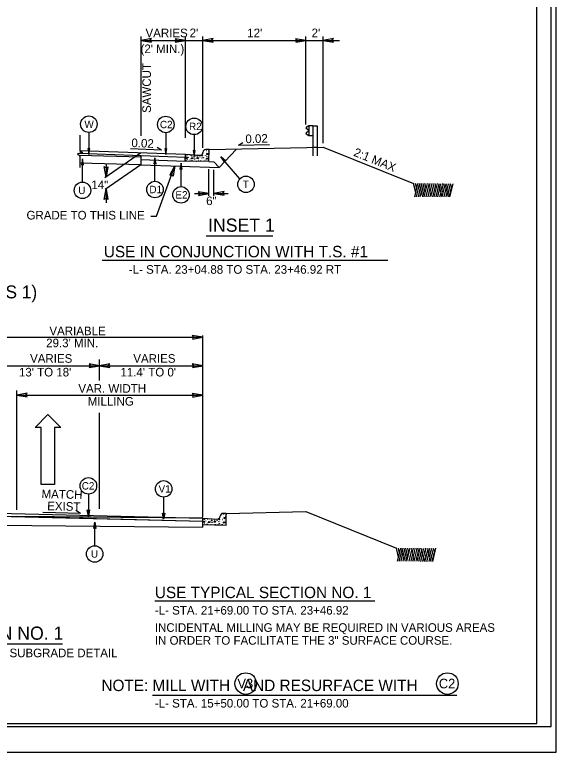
# Model space of a CAD drawing. Extents: x 573748 to 574632, y -54663 to -53209.
# Drawn here: x 574186.6 to 574281, y -53428.7 to -53300 of the extents above; entities that cross this region are included whole.
import ezdxf

# ---------------------------------------------------------------- set-up
doc = ezdxf.new("R2010")
doc.units = 0
for name, color, linetype in [('Prop Dimension', 7, 'Continuous'), ('Prop Dimension Text', 7, 'Continuous'), ('Prop Lane Arrow CELL', 7, 'Continuous'), ('Prop Terminator CELL', 7, 'Continuous'), ('Sheet Cutting Line CELL', 7, 'Continuous'), ('Sheet Plot Border Inside CELL', 7, 'Continuous'), ('Sheet Plot Border Outside CELL', 7, 'Continuous'), ('Sheet Typical CELL', 7, 'Continuous'), ('Typical Arrow Superelevation CELL', 7, 'Continuous'), ('Typical Curb CELL', 7, 'Continuous'), ('Typical Guardrail CELL', 7, 'Continuous'), ('Typical Hinge Slope Arterial CELL', 7, 'Continuous'), ('Typical ID Circle CELL', 7, 'Continuous'), ('Typical Pavement Slope CELL', 7, 'Continuous'), ('Typical Slope Point Local CELL', 7, 'Continuous'), ('Typical Terminator CELL', 7, 'Continuous'), ('Typical Text General CELL', 7, 'Continuous'), ('Typical Text ID Circle CELL', 7, 'Continuous'), ('Typical Text Label CELL', 7, 'Continuous')]:
    doc.layers.add(name, color=color, linetype=linetype)

msp = doc.modelspace()

# ---------------------------------------------------------------- linework, layer by layer
at = {"layer": 'Prop Dimension'}
for p, q in [((574208.6, -53321.18), (574208.6, -53303.84)), ((574216.33, -53321.5), (574216.33, -53303.84)), ((574219.33, -53323.24), (574219.33, -53303.84)), ((574237.33, -53319.18), (574237.33, -53303.84)), ((574240.33, -53322.43), (574240.33, -53303.84)), ((574208.6, -53304.5), (574216.33, -53304.5)), ((574216.33, -53304.5), (574219.33, -53304.5)), ((574219.33, -53304.5), (574237.33, -53304.5)), ((574237.33, -53304.5), (574243.16, -53304.5)), ((574197.88, -53321.01), (574197.88, -53323.78)), ((574198.38, -53324.08), (574197.52, -53324.27)), ((574197.52, -53324.27), (574197.88, -53324.62)), ((574197.77, -53324.52), (574208.6, -53324.8)), ((574197.88, -53323.78), (574198.38, -53324.08)), ((574197.88, -53324.62), (574197.88, -53326.68)), ((574208.48, -53324.17), (574202.29, -53328.47)), ((574197.88, -53325.87), (574208.6, -53326.14)), ((574208.56, -53326.22), (574202.35, -53330.54)), ((574202.48, -53325.99), (574202.48, -53328.34)), ((574208.6, -53326.14), (574208.6, -53325.92)), ((574220.38, -53331.64), (574220.38, -53326.95)), ((574221.27, -53331.64), (574221.27, -53327.1)), ((574202.48, -53330.45), (574202.48, -53332.85)), ((574217.87, -53331.21), (574220.38, -53331.21)), ((574221.27, -53331.21), (574223.77, -53331.21)), ((574174.33, -53356.27), (574219.33, -53356.27)), ((574219.33, -53387.71), (574219.33, -53356.01)), ((574201.33, -53363.84), (574201.33, -53360.17)), ((574183.33, -53361.26), (574201.33, -53361.26)), ((574201.33, -53361.26), (574219.33, -53361.26)), ((574186.93, -53386.44), (574186.93, -53365.58)), ((574186.93, -53366.41), (574219.33, -53366.41)), ((574201.33, -53386.26), (574201.33, -53369.46)), ((574219.33, -53387.86), (574174.33, -53387.48)), ((574219.33, -53389.03), (574219.33, -53387.86)), ((574219.33, -53387.86), (574221.84, -53388.02)), ((574219.33, -53388.11), (574219.33, -53387.86)), ((574219.33, -53387.86), (574219.33, -53387.86)), ((574222.37, -53387.54), (574222.37, -53387.51)), ((574223.43, -53387.04), (574222.89, -53387.03)), ((574223.02, -53387.73), (574223.05, -53387.92)), ((574223.34, -53387.83), (574223.02, -53387.73)), ((574223.05, -53387.92), (574223.34, -53387.83)), ((574223.43, -53387.04), (574237.33, -53386.73)), ((574223.43, -53389.14), (574223.43, -53387.04)), ((574237.33, -53386.73), (574253.1, -53393.1)), ((574174.33, -53389), (574219.33, -53389.45)), ((574219.33, -53389.45), (574219.33, -53389.03)), ((574223.43, -53389.14), (574219.33, -53389.03)), ((574219.37, -53388.56), (574219.55, -53388.32)), ((574219.62, -53388.56), (574219.37, -53388.56)), ((574219.55, -53388.32), (574219.62, -53388.56)), ((574220.3, -53388.66), (574220.44, -53388.42)), ((574220.65, -53388.59), (574220.3, -53388.66)), ((574220.44, -53388.42), (574220.65, -53388.59)), ((574221.32, -53388.58), (574221.5, -53388.33)), ((574221.57, -53388.57), (574221.32, -53388.58)), ((574221.5, -53388.33), (574221.57, -53388.57)), ((574222.92, -53388.73), (574223.05, -53388.49)), ((574223.27, -53388.65), (574222.92, -53388.73)), ((574223.05, -53388.49), (574223.27, -53388.65)), ((574253.48, -53394.65), (574253.1, -53393.1)), ((574253.3, -53395.38), (574253.86, -53393.09)), ((574253.65, -53393.96), (574253.44, -53393.1)), ((574254.7, -53395.38), (574254.13, -53393.1)), ((574254.7, -53394.16), (574254.44, -53393.1)), ((574255.12, -53394.63), (574254.74, -53393.1)), ((574254.93, -53395.38), (574255.5, -53393.1)), ((574255.28, -53393.97), (574255.07, -53393.1)), ((574256.38, -53395.38), (574255.81, -53393.1)), ((574256.71, -53395.32), (574256.17, -53393.1)), ((574256.89, -53394.61), (574256.52, -53393.1)), ((574256.7, -53395.38), (574257.26, -53393.1)), ((574257.05, -53393.94), (574256.84, -53393.1)), ((574258.07, -53395.42), (574257.5, -53393.13)), ((574258.16, -53394.56), (574257.8, -53393.13)), ((574258.07, -53394.1), (574258.31, -53393.13)), ((574258.16, -53393.24), (574258.13, -53393.13)), ((574258.2, -53393.2), (574258.17, -53393.1)), ((574259.17, -53395.42), (574258.59, -53393.13)), ((574259.44, -53395.35), (574258.89, -53393.13)), ((574259.61, -53394.69), (574259.22, -53393.13)), ((574259.43, -53395.42), (574259.99, -53393.12)), ((574259.78, -53394), (574259.56, -53393.13)), ((574253.6, -53395.38), (574254.15, -53393.17)), ((574253.94, -53395.38), (574254.31, -53393.82)), ((574254.97, -53395.24), (574254.7, -53394.16)), ((574255.3, -53395.38), (574255.84, -53393.2)), ((574255.65, -53395.38), (574256.01, -53393.9)), ((574257.04, -53395.38), (574257.57, -53393.21)), ((574257.34, -53395.42), (574257.7, -53393.94)), ((574258.09, -53393.97), (574258.07, -53393.88)), ((574258.08, -53395.42), (574258.62, -53393.25)), ((574258.43, -53395.42), (574258.8, -53393.94)), ((574254.26, -53395.38), (574254.48, -53394.48)), ((574255.99, -53395.38), (574256.18, -53394.59)), ((574257.7, -53395.42), (574257.88, -53394.65)), ((574258.79, -53395.42), (574258.97, -53394.65))]:
    msp.add_line(p, q, dxfattribs=at)
for points in [[(574210.26, -53335.17), (574211.28, -53335.17), (574214.48, -53326.41)], [(574219.33, -53387.86), (574186.93, -53387.58), (574219.33, -53388.37), (574219.33, -53388.11)]]:
    msp.add_lwpolyline(points, dxfattribs=at)
for centre in [(574219.66, -53387.96), (574222.95, -53387.19), (574223.28, -53387.65), (574223.4, -53387.27), (574219.37, -53388.92), (574219.38, -53388.1), (574219.62, -53388.75), (574219.62, -53388.07), (574219.73, -53388.99), (574219.82, -53388.37), (574220.1, -53388.87), (574220.2, -53388.04), (574220.45, -53388.15), (574220.46, -53388.96), (574220.78, -53389.01), (574220.81, -53388.36), (574220.85, -53388.16), (574220.92, -53388.66), (574220.97, -53388.23), (574221.13, -53388.57), (574221.2, -53388.04), (574221.22, -53389.07), (574221.4, -53388.16), (574221.56, -53388.93), (574221.81, -53388.09), (574221.86, -53388.3), (574221.99, -53388.99), (574222.17, -53388.49), (574222.24, -53388.13), (574222.23, -53388.82), (574222.28, -53388.03), (574222.35, -53389.06), (574222.43, -53388.44), (574222.72, -53388.94), (574222.81, -53388.1), (574223.06, -53388.22), (574223.08, -53389.03)]:
    msp.add_circle(centre, 0.0168, dxfattribs=at)
for centre, start, end in [((574221.87, -53387.52), 266.1351, 358.5196), ((574222.87, -53387.53), 88.5196, 178.5196)]:
    msp.add_arc(centre, 0.502, start, end, dxfattribs=at)
at = {"layer": 'Prop Lane Arrow CELL'}
for p, q in [((574190.09, -53372.02), (574192.3, -53369.78)), ((574192.3, -53369.78), (574194.58, -53372.02)), ((574191.16, -53372.02), (574190.09, -53372.02)), ((574191.16, -53382), (574191.16, -53372.02)), ((574194.58, -53372.02), (574193.51, -53372.02)), ((574193.51, -53372.02), (574193.51, -53382)), ((574193.51, -53382), (574191.16, -53382))]:
    msp.add_line(p, q, dxfattribs=at)
at = {"layer": 'Prop Terminator CELL'}
for points in [[(574210.4, -53304.17), (574208.6, -53304.5), (574210.42, -53304.8), (574210.18, -53304.48)], [(574214.54, -53304.83), (574216.33, -53304.5), (574214.52, -53304.2), (574214.75, -53304.52)], [(574221.13, -53304.17), (574219.33, -53304.5), (574221.15, -53304.8), (574220.91, -53304.48)], [(574235.54, -53304.83), (574237.33, -53304.5), (574235.52, -53304.2), (574235.75, -53304.52)], [(574242.13, -53304.17), (574240.33, -53304.5), (574242.15, -53304.8), (574241.91, -53304.48)], [(574202.79, -53326.54), (574202.48, -53328.34), (574202.16, -53326.53), (574202.48, -53326.76)], [(574213.57, -53328), (574214.48, -53326.41), (574214.16, -53328.22), (574213.94, -53327.9)], [(574202.17, -53332.25), (574202.48, -53330.45), (574202.8, -53332.26), (574202.48, -53332.03)], [(574218.58, -53331.54), (574220.38, -53331.21), (574218.56, -53330.91), (574218.8, -53331.23)], [(574223.07, -53330.87), (574221.27, -53331.21), (574223.08, -53331.5), (574222.85, -53331.19)], [(574217.54, -53356.61), (574219.33, -53356.27), (574217.52, -53355.98), (574217.75, -53356.29)], [(574199.54, -53361.59), (574201.33, -53361.26), (574199.52, -53360.96), (574199.75, -53361.28)], [(574203.13, -53360.92), (574201.33, -53361.26), (574203.15, -53361.55), (574202.91, -53361.24)], [(574217.54, -53361.59), (574219.33, -53361.26), (574217.52, -53360.96), (574217.75, -53361.28)], [(574188.72, -53366.07), (574186.93, -53366.41), (574188.74, -53366.7), (574188.51, -53366.39)], [(574217.54, -53366.74), (574219.33, -53366.41), (574217.52, -53366.11), (574217.75, -53366.43)]]:
    msp.add_lwpolyline(points, close=True, dxfattribs=at)
at = {"layer": 'Sheet Cutting Line CELL'}
msp.add_line((573944.17, -53428.71), (574280.97, -53428.71), dxfattribs=at)
at = {"layer": 'Sheet Plot Border Inside CELL'}
msp.add_lwpolyline([(574280.07, -53213.2), (573946.77, -53213.2), (573946.77, -53424.22), (574280.07, -53424.22)], close=True, dxfattribs=at)
at = {"layer": 'Sheet Plot Border Outside CELL'}
msp.add_lwpolyline([(574280.97, -53208.71), (573944.17, -53208.71), (573944.17, -53428.71), (574280.97, -53428.71)], close=True, dxfattribs=at)
at = {"layer": 'Sheet Typical CELL'}
msp.add_lwpolyline([(574277.57, -53213.71), (573977.57, -53213.71), (573977.57, -53423.71), (574277.57, -53423.71)], close=True, dxfattribs=at)
at = {"layer": 'Typical Arrow Superelevation CELL'}
for p, q in [((574225.57, -53322.81), (574226.35, -53322.33)), ((574212.15, -53323.67), (574206.76, -53323.44)), ((574212.15, -53323.67), (574211.38, -53323.18)), ((574225.57, -53322.81), (574230.97, -53322.67)), ((574198, -53387.03), (574197.22, -53386.55)), ((574198, -53387.03), (574191.48, -53386.87))]:
    msp.add_line(p, q, dxfattribs=at)
at = {"layer": 'Typical Curb CELL'}
for p, q in [((574220.43, -53323.56), (574219.89, -53323.55)), ((574220.38, -53325.66), (574220.43, -53323.56)), ((574216.3, -53325.55), (574216.33, -53324.38)), ((574216.33, -53324.38), (574218.84, -53324.55)), ((574216.37, -53325.09), (574216.55, -53324.84)), ((574216.55, -53324.84), (574216.62, -53325.08)), ((574218.32, -53325.1), (574218.5, -53324.85)), ((574218.5, -53324.85), (574218.57, -53325.09)), ((574219.37, -53324.06), (574219.37, -53324.04)), ((574220.02, -53324.25), (574220.05, -53324.44)), ((574220.34, -53324.35), (574220.02, -53324.25)), ((574220.05, -53324.44), (574220.34, -53324.35)), ((574220.38, -53325.66), (574216.3, -53325.55)), ((574216.62, -53325.08), (574216.37, -53325.09)), ((574217.3, -53325.18), (574217.44, -53324.95)), ((574217.65, -53325.11), (574217.3, -53325.18)), ((574217.44, -53324.95), (574217.65, -53325.11)), ((574218.57, -53325.09), (574218.32, -53325.1)), ((574219.92, -53325.25), (574220.05, -53325.01)), ((574220.27, -53325.18), (574219.92, -53325.25)), ((574220.05, -53325.01), (574220.27, -53325.18))]:
    msp.add_line(p, q, dxfattribs=at)
for centre in [(574216.38, -53324.62), (574216.62, -53324.59), (574216.66, -53324.48), (574216.82, -53324.89), (574217.2, -53324.56), (574217.45, -53324.67), (574217.81, -53324.88), (574217.85, -53324.68), (574217.97, -53324.76), (574218.2, -53324.57), (574218.4, -53324.68), (574218.81, -53324.61), (574218.86, -53324.83), (574219.24, -53324.66), (574219.28, -53324.55), (574219.81, -53324.63), (574219.95, -53323.71), (574220.06, -53324.74), (574220.28, -53324.17), (574220.4, -53323.79), (574216.37, -53325.44), (574216.62, -53325.27), (574216.73, -53325.51), (574217.1, -53325.39), (574217.46, -53325.48), (574217.78, -53325.53), (574217.92, -53325.19), (574218.13, -53325.1), (574218.22, -53325.59), (574218.56, -53325.45), (574218.99, -53325.51), (574219.17, -53325.01), (574219.23, -53325.34), (574219.35, -53325.58), (574219.44, -53324.96), (574219.72, -53325.46), (574220.08, -53325.55)]:
    msp.add_circle(centre, 0.0168, dxfattribs=at)
for centre, start, end in [((574219.87, -53324.05), 88.5196, 178.5196), ((574218.87, -53324.05), 266.1351, 358.5196)]:
    msp.add_arc(centre, 0.502, start, end, dxfattribs=at)
at = {"layer": 'Typical Guardrail CELL'}
for p, q in [((574237.82, -53319.4), (574237.38, -53319.71)), ((574238.56, -53319.4), (574237.82, -53319.4)), ((574237.82, -53319.4), (574237.82, -53321.14)), ((574238.56, -53319.4), (574238.56, -53323.13)), ((574238.56, -53319.4), (574239.31, -53319.4)), ((574239.31, -53319.4), (574239.31, -53323.13)), ((574237.82, -53320.2), (574237.38, -53319.9)), ((574237.82, -53320.34), (574237.38, -53320.65)), ((574237.82, -53321.14), (574237.38, -53320.84)), ((574237.82, -53320.27), (574237.82, -53320.2)), ((574237.82, -53320.27), (574237.82, -53320.34)), ((574238.56, -53321.14), (574237.82, -53321.14)), ((574238.56, -53323.13), (574239.31, -53323.13)), ((574238.56, -53323.13), (574238.56, -53324.64)), ((574239.31, -53323.13), (574239.31, -53324.64))]:
    msp.add_line(p, q, dxfattribs=at)
for centre, start, end in [((574237.45, -53319.8), 125.003, 235.0112), ((574237.45, -53320.74), 125.0059, 235.0366)]:
    msp.add_arc(centre, 0.116, start, end, dxfattribs=at)
at = {"layer": 'Typical Hinge Slope Arterial CELL'}
msp.add_line((574240.33, -53323.12), (574256.1, -53329.49), dxfattribs=at)
at = {"layer": 'Typical ID Circle CELL'}
for p, q in [((574199.48, -53320.58), (574199.48, -53324.4)), ((574212.89, -53320.62), (574212.89, -53324.44)), ((574217.84, -53320.95), (574217.84, -53324.77)), ((574225.8, -53328.65), (574222.49, -53324.83)), ((574198.36, -53329.23), (574198.36, -53325.15)), ((574211.01, -53329.07), (574211.01, -53324.99)), ((574215.55, -53330.02), (574215.55, -53325.93)), ((574199.4, -53383.67), (574199.4, -53387.5)), ((574212.52, -53384.2), (574212.52, -53388.03)), ((574200.5, -53392.67), (574200.5, -53388.58))]:
    msp.add_line(p, q, dxfattribs=at)
for centre, radius in [((574199.48, -53319.13), 1.44), ((574212.89, -53319.17), 1.44), ((574217.84, -53319.51), 1.44), ((574226.87, -53329.62), 1.44), ((574198.36, -53330.67), 1.44), ((574211.01, -53330.52), 1.44), ((574215.55, -53331.46), 1.44), ((574199.4, -53382.23), 1.44), ((574212.52, -53382.76), 1.44), ((574200.5, -53394.11), 1.44), ((574226.83, -53416.73), 1.88), ((574262, -53416.73), 1.88)]:
    msp.add_circle(centre, radius, dxfattribs=at)
at = {"layer": 'Typical Pavement Slope CELL'}
for p, q in [((574220.43, -53323.56), (574240.33, -53323.12)), ((574222.22, -53326.7), (574225.25, -53323.46)), ((574197.84, -53324.2), (574216.32, -53324.89)), ((574197.88, -53323.69), (574216.33, -53324.38)), ((574208.6, -53326.19), (574208.6, -53324.6)), ((574208.6, -53325.26), (574216.3, -53325.55)), ((574208.6, -53326.19), (574222.22, -53326.7)), ((574220.38, -53325.66), (574221.29, -53325.7)), ((574222.22, -53326.7), (574221.29, -53325.7)), ((574174.33, -53387.28), (574219.33, -53388.37)), ((574181.83, -53386.95), (574219.33, -53387.86))]:
    msp.add_line(p, q, dxfattribs=at)
at = {"layer": 'Typical Slope Point Local CELL'}
for p, q in [((574256.48, -53331.04), (574256.1, -53329.49)), ((574256.3, -53331.77), (574256.86, -53329.48)), ((574256.65, -53330.35), (574256.44, -53329.49)), ((574256.6, -53331.77), (574257.15, -53329.56)), ((574257.7, -53331.77), (574257.13, -53329.49)), ((574257.7, -53330.55), (574257.44, -53329.49)), ((574258.12, -53331.02), (574257.74, -53329.49)), ((574257.93, -53331.77), (574258.5, -53329.49)), ((574258.28, -53330.36), (574258.07, -53329.49)), ((574258.3, -53331.77), (574258.84, -53329.59)), ((574259.38, -53331.77), (574258.81, -53329.49)), ((574259.71, -53331.71), (574259.17, -53329.49)), ((574259.89, -53331), (574259.52, -53329.49)), ((574259.7, -53331.77), (574260.26, -53329.49)), ((574260.05, -53330.33), (574259.84, -53329.49)), ((574260.04, -53331.77), (574260.57, -53329.6)), ((574261.08, -53331.81), (574260.5, -53329.52)), ((574261.16, -53330.95), (574260.8, -53329.52)), ((574261.07, -53330.49), (574261.31, -53329.52)), ((574261.08, -53331.81), (574261.62, -53329.64)), ((574261.16, -53329.63), (574261.13, -53329.52)), ((574261.2, -53329.59), (574261.17, -53329.49)), ((574262.17, -53331.81), (574261.59, -53329.52)), ((574262.44, -53331.73), (574261.89, -53329.52)), ((574262.61, -53331.08), (574262.22, -53329.52)), ((574262.43, -53331.81), (574262.99, -53329.51)), ((574262.78, -53330.39), (574262.56, -53329.52)), ((574256.94, -53331.77), (574257.32, -53330.21)), ((574257.26, -53331.77), (574257.48, -53330.87)), ((574257.97, -53331.63), (574257.7, -53330.55)), ((574258.65, -53331.77), (574259.01, -53330.29)), ((574258.99, -53331.77), (574259.18, -53330.98)), ((574260.34, -53331.81), (574260.7, -53330.33)), ((574260.7, -53331.81), (574260.88, -53331.04)), ((574261.09, -53330.36), (574261.07, -53330.27)), ((574261.43, -53331.81), (574261.8, -53330.33)), ((574261.79, -53331.81), (574261.97, -53331.04))]:
    msp.add_line(p, q, dxfattribs=at)
at = {"layer": 'Typical Terminator CELL'}
for points in [[(574199.3, -53323.35), (574199.48, -53324.4), (574199.67, -53323.34), (574199.48, -53323.48)], [(574212.71, -53323.39), (574212.89, -53324.44), (574213.08, -53323.38), (574212.89, -53323.52)], [(574217.65, -53323.72), (574217.84, -53324.77), (574218.02, -53323.71), (574217.84, -53323.85)], [(574223.32, -53325.5), (574222.49, -53324.83), (574223.05, -53325.75), (574223.1, -53325.53)], [(574198.54, -53326.2), (574198.36, -53325.15), (574198.17, -53326.21), (574198.36, -53326.07)], [(574211.19, -53326.04), (574211.01, -53324.99), (574210.82, -53326.05), (574211.01, -53325.91)], [(574215.73, -53326.99), (574215.55, -53325.93), (574215.36, -53326.99), (574215.55, -53326.86)], [(574199.58, -53386.44), (574199.4, -53387.5), (574199.21, -53386.44), (574199.4, -53386.57)], [(574212.7, -53386.97), (574212.52, -53388.03), (574212.33, -53386.97), (574212.52, -53387.1)], [(574200.32, -53389.64), (574200.5, -53388.58), (574200.69, -53389.64), (574200.5, -53389.51)]]:
    msp.add_lwpolyline(points, close=True, dxfattribs=at)
at = {"layer": 'Typical Text General CELL'}
for p, q in [((574201.79, -53342.84), (574251.6, -53342.84)), ((574210.99, -53402.31), (574249.37, -53402.31)), ((574210.6, -53418.73), (574263.65, -53418.73))]:
    msp.add_line(p, q, dxfattribs=at)
at = {"layer": 'Typical Text Label CELL'}
for p, q in [((574219.91, -53338.61), (574231.58, -53338.61)), ((574158.69, -53409.8), (574194.9, -53409.8))]:
    msp.add_line(p, q, dxfattribs=at)

# ---------------------------------------------------------------- texts
at = {"layer": 'Prop Dimension'}
msp.add_text('GRADE TO THIS LINE', height=1.5, rotation=360, dxfattribs=at).set_placement((574188.61, -53335.75))
at = {"layer": 'Prop Dimension Text'}
for s, height, p in [('VARIES', 1.5, (574209.36, -53303.95)), ("2'", 1.5, (574217.05, -53303.94)), ("12'", 1.5, (574227.09, -53303.95)), ("2'", 1.5, (574238.32, -53303.94)), ("(2' MIN.)", 1.5, (574208.49, -53306.72)), ('14"', 1.5, (574199.92, -53330.45)), ('6"', 1.5, (574219.93, -53333.24)), ('INSET 1', 2.3, (574220.27, -53337.89)), ('-L- (US 1)', 2.25, (574177.26, -53349.51)), ('VARIABLE', 1.5, (574192.6, -53355.94)), ("29.3' MIN.", 1.5, (574192.04, -53358.04)), ('VARIES', 1.5, (574189.23, -53360.75)), ('VARIES', 1.5, (574207.23, -53360.75)), ("13' TO 18'", 1.5, (574187.29, -53363.14)), ("11.4' TO 0'", 1.5, (574204.99, -53363.14)), ('VAR. WIDTH', 1.5, (574197.65, -53365.98)), ('MILLING', 1.5, (574199.29, -53368.23)), ('TYPICAL SECTION NO. 1', 2.3, (574158.8, -53409.08))]:
    msp.add_text(s, height=height, dxfattribs=at).set_placement(p)
for s, rotation, p in [('SAWCUT', 90, (574210.3, -53317.15)), ('0.02', 1.5117, (574226.79, -53322.44)), ('0.02', 357.6243, (574206.87, -53323.1)), ('2:1 MAX', 338.0012, (574245.51, -53324.59)), ('MATCH', 358.6506, (574191.22, -53384.36)), ('EXIST', 358.6506, (574192.2, -53386.48))]:
    msp.add_text(s, height=1.5, rotation=rotation, dxfattribs=at).set_placement(p)
at = {"layer": 'Typical Text General CELL'}
for s, height, p in [('USE IN CONJUNCTION WITH T.S. #1', 2, (574202.09, -53342.35)), ('-L- STA. 23+04.88 TO STA. 23+46.92 RT', 1.5, (574206.45, -53345.22)), ('USE TYPICAL SECTION NO. 1', 2, (574210.99, -53401.82)), ('-L- STA. 21+69.00 TO STA. 23+46.92', 1.5, (574210.99, -53404.69)), ('INCIDENTAL MILLING MAY BE REQUIRED IN VARIOUS AREAS', 1.5, (574210.99, -53407.7)), ('IN ORDER TO FACILITATE THE 3" SURFACE COURSE.', 1.5, (574210.99, -53409.95)), ('SEE SHEET 2A-6 FOR AGGREGATE SUBGRADE DETAIL', 1.5, (574150.98, -53412.13)), ('NOTE: MILL WITH   AND RESURFACE WITH ', 2, (574201.67, -53418.04)), ('-L- STA. 15+50.00 TO STA. 21+69.00', 1.5, (574210.99, -53420.91))]:
    msp.add_text(s, height=height, dxfattribs=at).set_placement(p)
at = {"layer": 'Typical Text ID Circle CELL'}
for s, height, p in [('W', 1.29, (574198.71, -53319.78)), ('C2', 1.291, (574211.87, -53319.82)), ('R2', 1.291, (574216.95, -53320.15)), ('U', 1.29, (574197.64, -53331.32)), ('D1', 1.291, (574210.04, -53331.16)), ('T', 1.29, (574226.34, -53330.26)), ('E2', 1.291, (574214.57, -53332.1)), ('C2', 1.291, (574198.24, -53382.87)), ('V1', 1.291, (574211.63, -53383.4)), ('U', 1.29, (574199.83, -53394.75)), ('V3', 1.679, (574225.38, -53417.56)), ('C2', 1.679, (574260.5, -53417.56))]:
    msp.add_text(s, height=height, dxfattribs=at).set_placement(p)

doc.saveas('drawing.dxf')
